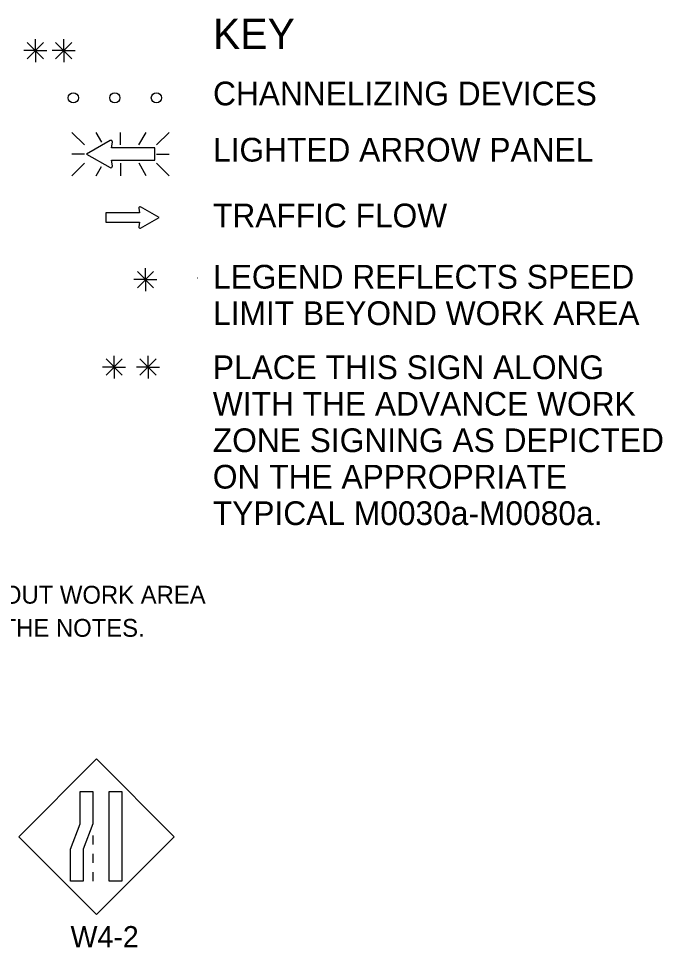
# Model space of a CAD drawing. Extents: x 16503 to 19508, y 5728 to 6974.
# Drawn here: x 18196 to 18448.8, y 6552.5 to 6916.9 of the extents above; entities that cross this region are included whole.
import ezdxf

# ---------------------------------------------------------------- set-up
doc = ezdxf.new("R2010")
doc.units = 0
for name, color, linetype in [('MT_SCRATCH_LEVEL_E', 7, 'Continuous'), ('TRAFFIC_SIGNS_PR', 7, 'Continuous'), ('TYPICAL_TEXT_DIMEN_EX', 7, 'Continuous'), ('TYPICAL_TEXT_DIMEN_PR', 7, 'Continuous')]:
    doc.layers.add(name, color=color, linetype=linetype)

msp = doc.modelspace()

# ---------------------------------------------------------------- linework, layer by layer
at = {"layer": 'MT_SCRATCH_LEVEL_E'}
for p, q in [((18243.57, 6840.73), (18230.31, 6840.73)), ((18230.31, 6840.73), (18230.31, 6836.99)), ((18243.25, 6842.51), (18243.57, 6840.73)), ((18251.18, 6838.88), (18243.94, 6842.99)), ((18230.31, 6836.99), (18243.57, 6836.99)), ((18243.57, 6836.99), (18243.25, 6835.21)), ((18243.94, 6834.73), (18251.18, 6838.88))]:
    msp.add_line(p, q, dxfattribs=at)
for centre, start, end in [((18243.71, 6842.58), 60.4248, 189.9638), ((18243.71, 6835.14), 170.0362, 299.7731)]:
    msp.add_arc(centre, 0.463, start, end, dxfattribs=at)
at = {"layer": 'TRAFFIC_SIGNS_PR'}
for p, q in [((18216.99, 6872.26), (18221.92, 6867.33)), ((18228.75, 6868.44), (18226.54, 6872.26)), ((18236.07, 6867.33), (18236.07, 6872.26)), ((18243.31, 6867.33), (18246.16, 6872.26)), ((18250.22, 6867.33), (18255.16, 6872.27)), ((18221.92, 6863.77), (18216.99, 6863.77)), ((18250.22, 6863.77), (18255.16, 6863.77)), ((18216.99, 6855.28), (18221.92, 6860.22)), ((18226.5, 6855.28), (18228.61, 6858.94)), ((18236.07, 6860.22), (18236.07, 6855.28)), ((18246.2, 6855.28), (18243.35, 6860.22)), ((18250.22, 6860.22), (18255.16, 6855.28)), ((18226.63, 6626.44), (18196.09, 6595.89)), ((18257.18, 6595.89), (18226.63, 6626.44)), ((18225.23, 6596.45), (18225.23, 6592.85)), ((18196.09, 6595.89), (18226.63, 6565.35)), ((18226.63, 6565.35), (18257.18, 6595.89)), ((18225.23, 6589.25), (18225.23, 6585.65)), ((18225.23, 6582.05), (18225.23, 6578.45))]:
    msp.add_line(p, q, dxfattribs=at)
for points in [[(18232, 6869.05), (18222.71, 6863.77), (18232, 6858.45)], [(18232.87, 6859.08), (18232.47, 6861.35), (18249.49, 6861.35), (18249.49, 6866.15), (18232.47, 6866.15), (18232.88, 6868.43)]]:
    msp.add_lwpolyline(points, dxfattribs=at)
for points in [[(18225.23, 6613.6), (18225.23, 6601.02), (18221.47, 6591.02), (18221.47, 6578.45), (18216.41, 6578.45), (18216.41, 6591.02), (18220.18, 6601.02), (18220.18, 6613.6)], [(18236.63, 6613.6), (18236.63, 6578.45), (18231.58, 6578.45), (18231.58, 6613.6)]]:
    msp.add_lwpolyline(points, close=True, dxfattribs=at)
for centre in [(18217.55, 6885.81), (18233.85, 6885.81), (18250.15, 6885.81)]:
    msp.add_circle(centre, 2, dxfattribs=at)
for centre, radius, start, end in [((18232.29, 6868.53), 0.598, 350.7308, 118.8916), ((18232.29, 6858.98), 0.597, 241.4833, 9.9593)]:
    msp.add_arc(centre, radius, start, end, dxfattribs=at)
at = {"layer": 'TYPICAL_TEXT_DIMEN_EX'}
for p, q in [((18236.76, 6783.35), (18230.38, 6776.97)), ((18230.39, 6783.35), (18236.76, 6776.97)), ((18233.57, 6780.16), (18233.57, 6784.62)), ((18243.71, 6783.35), (18250.08, 6776.97)), ((18250.08, 6783.35), (18243.71, 6776.97)), ((18246.89, 6780.16), (18246.89, 6784.62)), ((18233.57, 6780.16), (18229.04, 6780.16)), ((18233.57, 6780.16), (18236.76, 6780.16)), ((18233.57, 6780.16), (18238.05, 6780.16)), ((18233.57, 6780.16), (18233.57, 6775.66)), ((18246.89, 6780.16), (18242.36, 6780.16)), ((18246.89, 6780.16), (18250.08, 6780.16)), ((18246.89, 6780.16), (18251.37, 6780.16)), ((18246.89, 6780.16), (18246.89, 6775.66))]:
    msp.add_line(p, q, dxfattribs=at)
at = {"layer": 'TYPICAL_TEXT_DIMEN_PR'}
for p, q in [((18199.47, 6907.53), (18205.84, 6901.15)), ((18205.84, 6907.53), (18199.47, 6901.15)), ((18202.65, 6904.34), (18202.65, 6908.8)), ((18216.97, 6907.53), (18210.59, 6901.15)), ((18210.6, 6907.53), (18216.97, 6901.15)), ((18213.78, 6904.34), (18213.78, 6908.8)), ((18202.65, 6904.34), (18198.12, 6904.34)), ((18202.65, 6904.34), (18205.84, 6904.34)), ((18202.65, 6904.34), (18207.13, 6904.34)), ((18202.65, 6904.34), (18202.65, 6899.84)), ((18213.78, 6904.34), (18209.25, 6904.34)), ((18213.78, 6904.34), (18216.97, 6904.34)), ((18213.78, 6904.34), (18218.26, 6904.34)), ((18213.78, 6904.34), (18213.78, 6899.84)), ((18245.88, 6814.5), (18245.88, 6818.95)), ((18242.7, 6817.68), (18249.07, 6811.31)), ((18249.07, 6817.68), (18242.7, 6811.31)), ((18245.88, 6814.5), (18241.35, 6814.5)), ((18245.88, 6814.5), (18249.07, 6814.5)), ((18245.88, 6814.5), (18250.36, 6814.5)), ((18245.88, 6814.5), (18245.88, 6810))]:
    msp.add_line(p, q, dxfattribs=at)
msp.add_open_spline([(18266.22, 6815.19), (18266.24, 6815.19), (18266.24, 6815.19), (18266.24, 6815.19)], degree=2, dxfattribs=at)

# ---------------------------------------------------------------- texts
at = {"layer": 'TRAFFIC_SIGNS_PR'}
for s, height, p in [('PLACE THROUGHOUT WORK AREA', 7, (18109.3, 6687.36)), ('AS INDICATED IN THE NOTES.', 7, (18109.3, 6674.36)), ('W4-2', 8.37, (18216.46, 6552.48))]:
    msp.add_text(s, height=height, dxfattribs=at).set_placement(p)
at = {"layer": 'TYPICAL_TEXT_DIMEN_EX'}
for s, height, p in [('KEY', 12, (18272.39, 6904.92)), ('CHANNELIZING DEVICES', 9.3, (18272.39, 6882.87)), ('LIGHTED ARROW PANEL', 9.3, (18272.39, 6860.82)), ('TRAFFIC FLOW', 9.3, (18272.39, 6835.02)), ('LEGEND REFLECTS SPEED', 9.31, (18272.39, 6810.98)), ('LIMIT BEYOND WORK AREA', 9.31, (18272.39, 6796.67)), ('PLACE THIS SIGN ALONG', 9.31, (18272.3, 6775.44)), ('WITH THE ADVANCE WORK', 9.31, (18272.3, 6761.13)), ('ZONE SIGNING AS DEPICTED', 9.31, (18272.3, 6746.82)), ('ON THE APPROPRIATE', 9.31, (18272.3, 6732.51)), ('TYPICAL M0030a-M0080a.', 9.31, (18272.3, 6718.2))]:
    msp.add_text(s, height=height, dxfattribs=at).set_placement(p)

doc.saveas('drawing.dxf')
